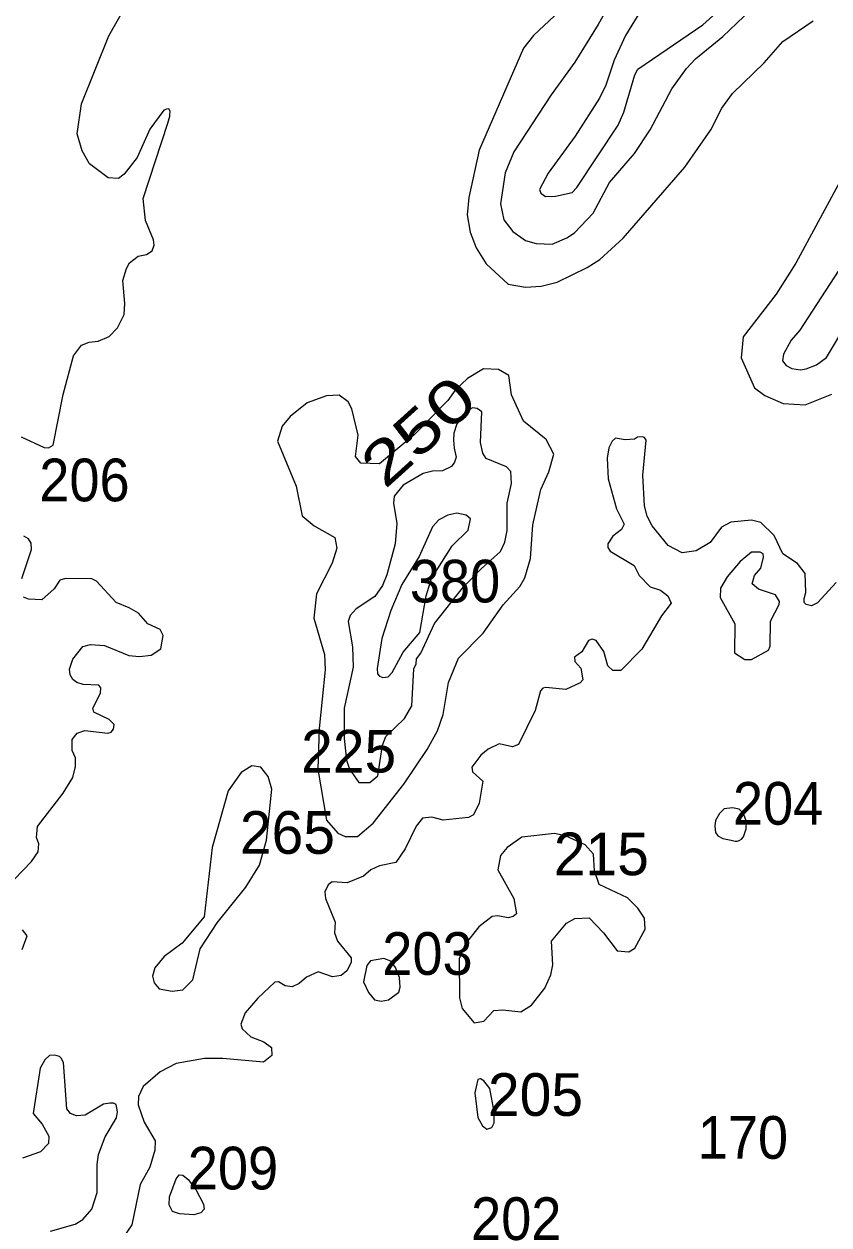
# Model space of a CAD drawing. Extents: x 499.9 to 555.3, y 9281.5 to 9336.8.
# Drawn here: x 539.58 to 542.601, y 9318.048 to 9322.551 of the extents above; entities that cross this region are included whole.
import ezdxf
from ezdxf.enums import TextEntityAlignment as Align

# ---------------------------------------------------------------- set-up
doc = ezdxf.new("R2010")
doc.units = 0
doc.header["$LTSCALE"] = 0.064
doc.layers.add('1', color=7, linetype='Continuous', lineweight=25)
doc.layers.add('2', color=7, linetype='Continuous', lineweight=13)
doc.layers.add('21', color=7, linetype='Continuous')
doc.layers.add('61', color=7, linetype='Continuous')

msp = doc.modelspace()

# ---------------------------------------------------------------- linework, layer by layer
at = {"layer": '1'}
for points in [[(541.6489, 9322.6563), (541.4914, 9322.5081), (541.4544, 9322.4612), (541.2877, 9322.0785), (541.2485, 9321.9011), (541.2432, 9321.8358), (541.2534, 9321.771), (541.2769, 9321.7117), (541.3137, 9321.6515), (541.3969, 9321.5762), (541.4616, 9321.5645), (541.5208, 9321.5679), (541.5805, 9321.5836), (541.6932, 9321.6383), (541.7399, 9321.6686), (541.8276, 9321.7481), (542.059, 9322.0142), (542.157, 9322.1545), (542.1984, 9322.2352), (542.2378, 9322.2902), (542.3566, 9322.406), (542.4267, 9322.4853), (542.5412, 9322.5635)], [(542.71, 9322.0874), (542.4761, 9321.6544), (542.4022, 9321.5381), (542.2779, 9321.3781), (542.2713, 9321.2994), (542.3215, 9321.187), (542.3595, 9321.1582), (542.4281, 9321.1284), (542.5117, 9321.1236), (542.611, 9321.163)]]:
    msp.add_lwpolyline(points, dxfattribs=at)
for points in [[(541.2105, 9320.1733), (541.3029, 9320.2675), (541.3772, 9320.3733), (541.4407, 9320.4427), (541.4585, 9320.4749), (541.4801, 9320.5474), (541.4897, 9320.6739), (541.5185, 9320.8053), (541.5486, 9320.8722), (541.5673, 9320.9381), (541.5385, 9320.9934), (541.4545, 9321.0624), (541.4088, 9321.1611), (541.3987, 9321.2331), (541.36, 9321.2556), (541.3044, 9321.2586), (541.2438, 9321.2226), (541.1981, 9321.1788), (541.1696, 9321.1396), (541.0435, 9321.011), (540.9134, 9320.9025), (540.8439, 9320.9042), (540.8237, 9320.9295), (540.8342, 9321.0097), (540.8104, 9321.1082), (540.796, 9321.1341), (540.7619, 9321.1599), (540.7147, 9321.1569), (540.6425, 9321.131), (540.5784, 9321.0795), (540.5481, 9321.043), (540.5304, 9320.9867), (540.6013, 9320.8188), (540.6239, 9320.7075), (540.6685, 9320.6701), (540.7457, 9320.6256), (540.7538, 9320.5858), (540.7356, 9320.5291), (540.6769, 9320.4145), (540.6671, 9320.3231), (540.707, 9320.187), (540.7097, 9320.1298), (540.6871, 9319.9103), (540.6827, 9319.7574), (540.7149, 9319.5665), (540.7572, 9319.5169), (540.785, 9319.505), (540.8313, 9319.5054), (540.8896, 9319.5543), (541.0056, 9319.701), (541.093, 9319.8305), (541.1312, 9319.9005), (541.1524, 9319.9626), (541.1731, 9320.0827)], [(540.4124, 9319.3153), (540.463, 9319.3973), (540.4898, 9319.491), (540.5095, 9319.6827), (540.4963, 9319.73), (540.4689, 9319.765), (540.4346, 9319.7695), (540.395, 9319.7451), (540.3456, 9319.6757), (540.2857, 9319.4633), (540.2555, 9319.2042), (540.1734, 9319.1049), (540.1052, 9319.0544), (540.0711, 9319.013), (540.0621, 9318.9812), (540.0681, 9318.9563), (540.0868, 9318.9336), (540.136, 9318.9254), (540.175, 9318.9298), (540.2127, 9318.9668), (540.241, 9319.0834), (540.3047, 9319.1817)]]:
    msp.add_lwpolyline(points, close=True, dxfattribs=at)
at = {"layer": '2'}
for points in [[(541.8924, 9322.8297), (541.7348, 9322.5496), (541.6468, 9322.4087), (541.5577, 9322.2854), (541.4184, 9322.0723), (541.385, 9321.9934), (541.3674, 9321.8773), (541.3805, 9321.817), (541.4145, 9321.7736), (541.4612, 9321.7397), (541.5017, 9321.7283), (541.5613, 9321.7254), (541.6171, 9321.7491), (541.6457, 9321.7682), (541.7157, 9321.8414), (541.7763, 9321.9575), (541.8712, 9322.0658), (541.929, 9322.1549), (542.0107, 9322.3084), (542.0654, 9322.385), (542.0996, 9322.4209), (542.2021, 9322.5045), (542.3336, 9322.6297)], [(541.9762, 9322.7359), (541.8368, 9322.5082), (541.7938, 9322.4159), (541.7626, 9322.3222), (541.7396, 9322.2728), (541.6478, 9322.1301), (541.5471, 9321.9926), (541.5145, 9321.9311), (541.5188, 9321.9164), (541.5362, 9321.9051), (541.5744, 9321.9056), (541.6373, 9321.9196), (541.6548, 9321.9379), (541.8099, 9322.1716), (541.8309, 9322.2204), (541.8715, 9322.361), (541.8835, 9322.3813), (542.1275, 9322.5486), (542.4712, 9322.8589)], [(540.1143, 9322.2323), (540.1046, 9322.2283), (540.0515, 9322.157), (540.0038, 9322.0501), (539.9555, 9321.9879), (539.9341, 9321.972), (539.8951, 9321.9743), (539.8257, 9322.0271), (539.7977, 9322.0761), (539.779, 9322.1393), (539.795, 9322.2514), (539.8974, 9322.5067), (540.0389, 9322.7566)], [(540.1192, 9322.1797), (540.1265, 9322.2055), (540.1272, 9322.2089), (540.1282, 9322.2246), (540.1235, 9322.233), (540.1143, 9322.2323)], [(539.5695, 9321.0039), (539.6547, 9320.963), (539.6721, 9320.9616), (539.6889, 9320.9722), (539.7265, 9321.1627), (539.7659, 9321.3076), (539.7954, 9321.3468), (539.8235, 9321.358), (539.8584, 9321.3625), (539.8991, 9321.3796), (539.9299, 9321.4117), (539.9554, 9321.4618), (539.9585, 9321.5032), (539.9507, 9321.589), (539.9648, 9321.6351), (539.9753, 9321.6555), (540.008, 9321.6804), (540.0397, 9321.6874), (540.0603, 9321.7013), (540.068, 9321.7214), (540.0651, 9321.7426), (540.0349, 9321.8151), (540.0272, 9321.8964), (540.1192, 9322.1797)], [(542.6514, 9321.6496), (542.4908, 9321.4038), (542.4591, 9321.3655), (542.4298, 9321.3132), (542.4262, 9321.2887), (542.4395, 9321.2714), (542.4608, 9321.2591), (542.4936, 9321.2541), (542.5147, 9321.2585), (542.5535, 9321.2736), (542.5915, 9321.301), (542.6717, 9321.4344)], [(541.8814, 9321.0022), (541.87, 9320.9949), (541.8356, 9320.9927), (541.7993, 9320.9987), (541.7869, 9320.987), (541.7749, 9320.9619), (541.7683, 9320.923), (541.7716, 9320.8459), (541.8031, 9320.7328), (541.8314, 9320.6757), (541.8222, 9320.6558), (541.7888, 9320.6308), (541.7704, 9320.6022), (541.7703, 9320.5883), (541.7792, 9320.5753), (541.8694, 9320.5208), (541.8882, 9320.4832), (541.9298, 9320.4406), (541.9688, 9320.4279), (541.9963, 9320.4074), (542.0081, 9320.3803), (541.9716, 9320.3318), (541.8987, 9320.2069), (541.8195, 9320.1271), (541.7891, 9320.1272), (541.7709, 9320.1444), (541.755, 9320.1979), (541.727, 9320.2395), (541.7114, 9320.2442), (541.6985, 9320.2399), (541.6735, 9320.1971), (541.6459, 9320.1774), (541.6461, 9320.1608), (541.6691, 9320.1356), (541.6772, 9320.0924), (541.6671, 9320.0805), (541.6132, 9320.0557), (541.538, 9320.0636), (541.5265, 9320.0606), (541.5182, 9320.0515), (541.4974, 9319.9769), (541.4354, 9319.85), (541.4132, 9319.8416), (541.3624, 9319.8527), (541.3215, 9319.8326), (541.2935, 9319.8099), (541.2607, 9319.7652), (541.2623, 9319.7476), (541.3015, 9319.7125), (541.2875, 9319.6292), (541.2662, 9319.5859), (541.2471, 9319.5765), (541.1524, 9319.5657), (541.1101, 9319.5768), (541.0756, 9319.5738), (541.0518, 9319.544), (541.0106, 9319.4589), (540.9748, 9319.4077), (540.9136, 9319.3944), (540.8809, 9319.3795), (540.8541, 9319.3563), (540.7925, 9319.3316), (540.7361, 9319.3345), (540.7216, 9319.3239), (540.7088, 9319.2972), (540.7111, 9319.2721), (540.7474, 9319.1836), (540.7453, 9319.1431), (540.7566, 9319.1128), (540.8069, 9319.0501), (540.807, 9319.0323), (540.7905, 9319.0008), (540.7703, 9318.9841), (540.7378, 9318.9786), (540.6832, 9318.9971), (540.64, 9318.9773), (540.6126, 9318.9538), (540.5862, 9318.9416), (540.5593, 9318.9454), (540.5344, 9318.9599), (540.5204, 9318.9588), (540.4567, 9318.8992), (540.41, 9318.8436), (540.3937, 9318.8012), (540.3984, 9318.7836), (540.4306, 9318.7537), (540.4791, 9318.7345), (540.5085, 9318.7142), (540.5099, 9318.6832), (540.4788, 9318.6593), (540.3263, 9318.6725), (540.2563, 9318.6725), (540.1506, 9318.6531), (540.0901, 9318.6225), (540.0266, 9318.5671)], [(541.9084, 9320.7448), (541.902, 9320.8602), (541.9142, 9320.9911), (541.9082, 9321.0008), (541.9005, 9321.0038), (541.8814, 9321.0022)], [(542.6278, 9320.4573), (542.5576, 9320.3806), (542.5343, 9320.3701), (542.5153, 9320.3753), (542.5076, 9320.3825), (542.5069, 9320.3968), (542.513, 9320.4192), (542.5109, 9320.4909), (542.4823, 9320.5286), (542.4277, 9320.5647), (542.3952, 9320.6333), (542.3442, 9320.6823), (542.3093, 9320.6906), (542.2324, 9320.6839), (542.1966, 9320.665), (542.1543, 9320.6075), (542.1017, 9320.576), (542.0494, 9320.5684), (541.9969, 9320.5957), (541.9366, 9320.6691), (541.9182, 9320.706), (541.9084, 9320.7448)], [(539.5713, 9320.4718), (539.6075, 9320.5815), (539.6065, 9320.6045), (539.5962, 9320.6214), (539.5788, 9320.6314)], [(539.5118, 9319.3108), (539.6079, 9319.4105), (539.6328, 9319.4477), (539.6354, 9319.4772), (539.6262, 9319.501), (539.6299, 9319.5422), (539.7263, 9319.6674), (539.7628, 9319.7263), (539.7723, 9319.7676), (539.7724, 9319.7993), (539.7601, 9319.8274), (539.7604, 9319.8681), (539.7789, 9319.8925), (539.8076, 9319.9025), (539.8937, 9319.8925), (539.9069, 9319.8966), (539.915, 9319.9071), (539.918, 9319.9251), (539.8991, 9319.9441), (539.8418, 9319.9704), (539.8382, 9319.9863), (539.867, 9320.0427), (539.868, 9320.0618), (539.861, 9320.072), (539.8022, 9320.075), (539.7784, 9320.0819), (539.7623, 9320.0932), (539.7531, 9320.1115), (539.7508, 9320.1322), (539.7623, 9320.1698), (539.8002, 9320.2168), (539.8295, 9320.2245), (539.882, 9320.2213), (539.9731, 9320.1841), (540.013, 9320.1799), (540.0563, 9320.1848), (540.0936, 9320.2087), (540.1022, 9320.259), (540.09, 9320.281), (540.0439, 9320.3022), (540.0089, 9320.3421), (539.9745, 9320.3627), (539.9249, 9320.3825), (539.8518, 9320.4618), (539.8344, 9320.4706), (539.735, 9320.4725), (539.7143, 9320.4655), (539.6922, 9320.4339), (539.6466, 9320.3919), (539.5962, 9320.3945), (539.5773, 9320.4024)], [(539.5727, 9319.0817), (539.591, 9319.1329), (539.5734, 9319.1547)], [(539.6792, 9318.0249), (539.772, 9318.0517), (539.8007, 9318.0689), (539.8341, 9318.107), (539.8536, 9318.1704), (539.8537, 9318.2747), (539.8592, 9318.3127), (539.8847, 9318.3782), (539.9267, 9318.4505), (539.9305, 9318.4719), (539.9252, 9318.4998), (539.9154, 9318.5049), (539.9018, 9318.5052), (539.8782, 9318.501), (539.8089, 9318.4596), (539.7761, 9318.458), (539.7537, 9318.4658), (539.7406, 9318.4839), (539.7279, 9318.6574), (539.7191, 9318.6736), (539.7125, 9318.6805), (539.6948, 9318.6854), (539.675, 9318.6838), (539.6579, 9318.6677), (539.6402, 9318.6367), (539.6142, 9318.4664), (539.6482, 9318.4258), (539.6729, 9318.3814), (539.6716, 9318.3539), (539.6417, 9318.3226), (539.5735, 9318.2992)], [(540.0266, 9318.5671), (540.009, 9318.5306), (540.0079, 9318.4982), (540.0303, 9318.4339), (540.0713, 9318.3635), (540.071, 9318.329)], [(540.071, 9318.329), (540.0521, 9318.2645), (540.0155, 9318.1999), (539.9845, 9318.0483), (539.9171, 9317.9501)]]:
    msp.add_lwpolyline(points, dxfattribs=at)
for points in [[(541.069, 9320.1927), (541.1204, 9320.3038), (541.2289, 9320.4405), (541.2948, 9320.5085), (541.368, 9320.5738), (541.3846, 9320.608), (541.3925, 9320.6525), (541.3923, 9320.7545), (541.4085, 9320.8283), (541.4062, 9320.873), (541.3898, 9320.8911), (541.3141, 9320.9225), (541.3009, 9320.9418), (541.2924, 9320.982), (541.2971, 9321.0967), (541.2804, 9321.1101), (541.2621, 9321.1118), (541.245, 9321.1026), (541.2299, 9321.0863), (541.2037, 9321.0524), (541.1928, 9321.017), (541.1908, 9320.9908), (541.1939, 9320.9614), (541.2011, 9320.9272), (541.1951, 9320.9087), (541.184, 9320.8927), (541.1497, 9320.8759), (541.1125, 9320.8752), (541.0774, 9320.8665), (541.0028, 9320.8226), (540.9681, 9320.7811), (540.9663, 9320.7543), (540.9787, 9320.6787), (540.9727, 9320.6017), (540.9412, 9320.4855), (540.925, 9320.4464), (540.8958, 9320.4044), (540.8265, 9320.3584), (540.8036, 9320.3334), (540.7962, 9320.3109), (540.8118, 9320.2157), (540.8149, 9320.14), (540.7815, 9319.9865), (540.7816, 9319.8719), (540.7895, 9319.7911), (540.8011, 9319.7574), (540.8359, 9319.7075), (540.8769, 9319.7075), (540.9079, 9319.7328), (540.9249, 9319.847), (540.9377, 9319.8803), (541.0073, 9319.9475), (541.035, 9319.9946), (541.0421, 9320.1337), (541.0518, 9320.1528), (541.0527, 9320.1708)], [(541.065, 9320.2695), (541.089, 9320.4074), (541.1086, 9320.472), (541.1869, 9320.5944), (541.2463, 9320.6533), (541.2556, 9320.6956), (541.239, 9320.7098), (541.2041, 9320.7174), (541.1699, 9320.7096), (541.1366, 9320.6921), (541.1131, 9320.6658), (541.062, 9320.5545), (540.998, 9320.4503), (540.9562, 9320.352), (540.923, 9320.2475), (540.9043, 9320.1344), (540.9067, 9320.1146), (540.914, 9320.1054), (540.9256, 9320.1007), (540.9466, 9320.1032), (540.9616, 9320.1201), (541.0024, 9320.1966)], [(542.3813, 9320.3118), (542.414, 9320.3748), (542.4143, 9320.3861), (542.4003, 9320.4112), (542.3357, 9320.4327), (542.3117, 9320.4525), (542.3204, 9320.483), (542.3444, 9320.511), (542.3553, 9320.5527), (542.3532, 9320.5651), (542.3423, 9320.5707), (542.3096, 9320.5711), (542.2675, 9320.5358), (542.2187, 9320.479), (542.1935, 9320.436), (542.1919, 9320.4011), (542.2471, 9320.3017), (542.2463, 9320.1937), (542.2847, 9320.1687), (542.3101, 9320.169), (542.3729, 9320.2039), (542.3792, 9320.2187)], [(542.2328, 9319.4914), (542.2479, 9319.4877), (542.2564, 9319.4877), (542.263, 9319.4895), (542.2725, 9319.4952), (542.2791, 9319.5037), (542.2895, 9319.5331), (542.2905, 9319.5614), (542.2801, 9319.5898), (542.264, 9319.6078), (542.2384, 9319.6125), (542.2072, 9319.6087), (542.1892, 9319.5917), (542.1741, 9319.5643), (542.1722, 9319.5435), (542.1751, 9319.5198), (542.1836, 9319.5075), (542.2015, 9319.4971)], [(541.9103, 9319.1579), (541.9079, 9319.1992), (541.8828, 9319.2358), (541.8442, 9319.2744), (541.7377, 9319.3246), (541.7199, 9319.3764), (541.717, 9319.438), (541.6859, 9319.4742), (541.6122, 9319.507), (541.5709, 9319.516), (541.4473, 9319.5018), (541.3931, 9319.4639), (541.3675, 9319.4337), (541.358, 9319.3795), (541.418, 9319.2724), (541.4272, 9319.2155), (541.4154, 9319.2047), (541.3965, 9319.1996), (541.3579, 9319.2069), (541.3367, 9319.2053), (541.2864, 9319.1662), (541.2351, 9319.1007), (541.2129, 9319.0457), (541.2144, 9318.8994), (541.2241, 9318.8605), (541.2687, 9318.8065), (541.3048, 9318.812), (541.3426, 9318.8523), (541.3767, 9318.8555), (541.4444, 9318.8478), (541.4842, 9318.8728), (541.5339, 9318.9361), (541.5569, 9318.9862), (541.5644, 9319.0235), (541.559, 9319.113), (541.6151, 9319.1797), (541.6467, 9319.1974), (541.701, 9319.1999), (541.7548, 9319.1434), (541.805, 9319.0762), (541.8497, 9319.0721), (541.872, 9319.0856)], [(540.8655, 9319.0209), (540.8537, 9318.9593), (540.872, 9318.9196), (540.8948, 9318.893), (540.9204, 9318.8873), (540.9475, 9318.8927), (540.9861, 9318.9206), (540.9914, 9318.9397), (540.9886, 9318.9757), (540.9736, 9319.0133), (540.9556, 9319.0371), (540.9294, 9319.0477), (540.8797, 9319.0388)], [(541.2769, 9318.5664), (541.2709, 9318.5437), (541.283, 9318.4507), (541.3005, 9318.4196), (541.3166, 9318.4075), (541.3346, 9318.4143), (541.3442, 9318.4312), (541.3441, 9318.472), (541.3274, 9318.5594), (541.3053, 9318.5886), (541.2927, 9318.5961), (541.2829, 9318.5939)], [(540.1633, 9318.0904), (540.1364, 9318.0986), (540.1247, 9318.124), (540.1253, 9318.1532), (540.1502, 9318.2214), (540.1615, 9318.2359), (540.1753, 9318.2356), (540.1954, 9318.2194), (540.2244, 9318.181), (540.2536, 9318.1267), (540.2553, 9318.1073), (540.2433, 9318.0933), (540.2171, 9318.0857)]]:
    msp.add_lwpolyline(points, close=True, dxfattribs=at)

# ---------------------------------------------------------------- texts
at = {"layer": '21', "width": 0.95}
for s, p in [('206', (539.6369, 9320.7617)), ('380', (541.0275, 9320.3824)), ('204', (542.24, 9319.5492)), ('203', (540.9241, 9318.9861)), ('170', (542.1078, 9318.2965)), ('209', (540.1943, 9318.1816)), ('202', (541.2574, 9317.992))]:
    msp.add_text(s, height=0.16, dxfattribs=at).set_placement(p)
at = {"layer": '21'}
for s, p in [('225', (540.6195, 9319.7446)), ('265', (540.3897, 9319.44)), ('215', (541.5677, 9319.3596)), ('205', (541.3206, 9318.4574))]:
    msp.add_text(s, height=0.16, dxfattribs=at).set_placement(p)
at = {"layer": '61', "width": 1.35}
msp.add_text('250', height=0.16, rotation=42.089, dxfattribs=at).set_placement((541.1127, 9320.9657), align=Align.CENTER)

doc.saveas('drawing.dxf')
